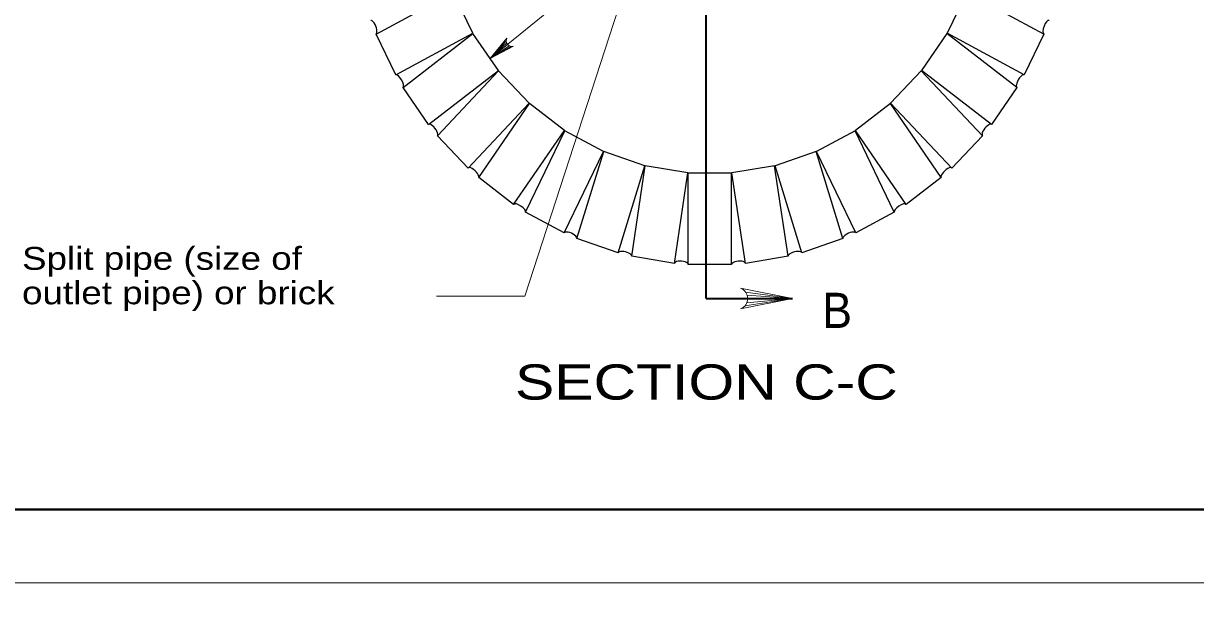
# Model space of a CAD drawing. Extents: x 1083.1 to 1117.1, y 697.4 to 741.4.
# Drawn here: x 1090.06 to 1098.04, y 719.1 to 723.17 of the extents above; entities that cross this region are included whole.
import ezdxf

# ---------------------------------------------------------------- set-up
doc = ezdxf.new("R2010")
doc.units = 0
doc.header["$LTSCALE"] = 0.062
doc.linetypes.add('LONG_DASHED', pattern=[7.5, 6, -1.5])
doc.layers.add('1', color=7, linetype='Continuous', lineweight=13)

msp = doc.modelspace()

# ---------------------------------------------------------------- linework, layer by layer
at = {"layer": '1', "lineweight": 35}
for p, q in [((1094.71067, 723.14725), (1094.71067, 723.88192)), ((1094.71067, 721.52408), (1094.71067, 723.14725)), ((1094.71067, 721.29192), (1094.71067, 721.52408)), ((1094.71067, 721.29192), (1095.29792, 721.29192))]:
    msp.add_line(p, q, dxfattribs=at)
at = {"layer": '1', "lineweight": 25}
for p, q in [((1092.46108, 723.09508), (1092.98608, 723.37833)), ((1093.11983, 723.10042), (1092.98608, 723.37833)), ((1096.48442, 723.37833), (1096.35067, 723.10042)), ((1097.00942, 723.09508), (1096.48442, 723.37833)), ((1092.59483, 722.81717), (1092.46108, 723.09508)), ((1092.59483, 722.81717), (1093.11983, 723.10042)), ((1092.64442, 722.73142), (1093.12117, 723.09808)), ((1093.29433, 722.84575), (1093.12117, 723.09808)), ((1096.34933, 723.09808), (1096.17617, 722.84575)), ((1096.826, 722.73142), (1096.34933, 723.09808)), ((1096.87567, 722.81717), (1096.35067, 723.10042)), ((1097.00942, 723.09508), (1096.87567, 722.81717)), ((1092.81767, 722.47908), (1093.29433, 722.84575)), ((1092.87933, 722.40258), (1093.296, 722.84367)), ((1093.50433, 722.62308), (1093.296, 722.84367)), ((1096.1745, 722.84367), (1095.96617, 722.62308)), ((1096.59117, 722.40258), (1096.1745, 722.84367)), ((1096.65283, 722.47908), (1096.17617, 722.84575)), ((1092.81767, 722.47908), (1092.64442, 722.73142)), ((1096.826, 722.73142), (1096.65283, 722.47908)), ((1093.08767, 722.182), (1093.50433, 722.62308)), ((1093.15992, 722.11667), (1093.50625, 722.62133)), ((1093.74467, 722.438), (1093.50625, 722.62133)), ((1095.96417, 722.62133), (1095.72583, 722.438)), ((1096.31058, 722.11667), (1095.96417, 722.62133)), ((1096.38283, 722.182), (1095.96617, 722.62308)), ((1093.39825, 721.93333), (1093.74467, 722.438)), ((1093.47933, 721.88075), (1093.74683, 722.43658)), ((1094.00933, 722.295), (1093.74683, 722.43658)), ((1095.72367, 722.43658), (1095.46117, 722.295)), ((1095.99117, 721.88075), (1095.72367, 722.43658)), ((1096.07217, 721.93333), (1095.72583, 722.438)), ((1093.08767, 722.182), (1092.87933, 722.40258)), ((1096.59117, 722.40258), (1096.38283, 722.182)), ((1093.74183, 721.73917), (1094.00933, 722.295)), ((1093.82958, 721.70067), (1094.01167, 722.29392)), ((1094.29192, 722.19758), (1094.01167, 722.29392)), ((1095.45883, 722.29392), (1095.17858, 722.19758)), ((1095.64092, 721.70067), (1095.45883, 722.29392)), ((1095.72867, 721.73917), (1095.46117, 722.295)), ((1094.10983, 721.60425), (1094.29192, 722.19758)), ((1094.20217, 721.58075), (1094.29442, 722.19692)), ((1094.58542, 722.14817), (1094.29442, 722.19692)), ((1095.17608, 722.19692), (1094.88508, 722.14817)), ((1095.26825, 721.58075), (1095.17608, 722.19692)), ((1095.36067, 721.60425), (1095.17858, 722.19758)), ((1093.39825, 721.93333), (1093.15992, 722.11667)), ((1094.49317, 721.532), (1094.58542, 722.14817)), ((1094.88258, 722.14792), (1094.58792, 722.14792)), ((1094.58792, 721.52408), (1094.58792, 722.14792)), ((1094.88258, 721.52408), (1094.88258, 722.14792)), ((1094.97725, 721.532), (1094.88508, 722.14817)), ((1096.31058, 722.11667), (1096.07217, 721.93333)), ((1093.74183, 721.73917), (1093.47933, 721.88075)), ((1095.99117, 721.88075), (1095.72867, 721.73917)), ((1094.10983, 721.60425), (1093.82958, 721.70067)), ((1095.64092, 721.70067), (1095.36067, 721.60425)), ((1094.49317, 721.532), (1094.20217, 721.58075)), ((1095.26825, 721.58075), (1094.97725, 721.532)), ((1094.88258, 721.52408), (1094.58792, 721.52408))]:
    msp.add_line(p, q, dxfattribs=at)
at = {"layer": '1'}
for p, q in [((1093.71942, 723.32042), (1093.23758, 722.92842)), ((1093.34775, 723.04692), (1093.23758, 722.92842)), ((1093.35058, 723.03492), (1093.23758, 722.92842)), ((1093.35642, 723.02508), (1093.23758, 722.92842)), ((1093.36767, 723.01567), (1093.23758, 722.92842)), ((1093.379, 723.0115), (1093.23758, 722.92842)), ((1094.9775, 721.33675), (1095.29792, 721.29192)), ((1094.98833, 721.3145), (1095.29792, 721.29192)), ((1094.97367, 721.24233), (1095.29792, 721.29192)), ((1094.98592, 721.26308), (1095.29792, 721.29192)), ((1094.99158, 721.29192), (1095.29792, 721.29192))]:
    msp.add_line(p, q, dxfattribs=at)
at = {"layer": '1', "linetype": 'LONG_DASHED'}
for points in [[(1083.12642, 719.35408), (1117.12642, 719.35408), (1117.12642, 741.35408), (1083.12642, 741.35408)], [(1083.12642, 697.35408), (1117.12642, 697.35408), (1117.12642, 719.35408), (1083.12642, 719.35408)]]:
    msp.add_lwpolyline(points, close=True, dxfattribs=at)
at = {"layer": '1', "lineweight": 25}
msp.add_lwpolyline([(1116.62642, 719.85408), (1085.12642, 719.85408), (1085.12642, 740.85408)], dxfattribs=at)
at = {"layer": '1', "lineweight": 40}
msp.add_lwpolyline([(1085.12642, 740.85408), (1116.62642, 740.85408), (1116.62642, 719.85408), (1085.12642, 719.85408)], close=True, dxfattribs=at)
at = {"layer": '1'}
for points in [[(1094.17225, 723.45483), (1093.47458, 721.3085), (1092.87242, 721.3085)], [(1093.39725, 723.01267), (1093.23758, 722.92842), (1093.35258, 723.06758)], [(1094.94392, 721.22108), (1095.29792, 721.29192), (1094.94392, 721.36267)]]:
    msp.add_lwpolyline(points, dxfattribs=at)
for centre, radius, start, end in [((1093.38596, 723.04916), 0.0382, 151.21802, 287.04414), ((1094.91536, 721.29196), 0.0764, 292.08605, 67.91218)]:
    msp.add_arc(centre, radius, start, end, dxfattribs=at)
at = {"layer": '1', "lineweight": 25}
for centre, major_axis, ratio, start_param, end_param in [((1092.44287, 723.14158), (-0.01791, 0.04658), 0.355583, 3.1580272, 6.2996199), ((1097.02761, 723.14157), (-0.01791, -0.04658), 0.355581, 3.1251606, 6.2667532), ((1092.61963, 722.7743), (-0.0245, 0.04308), 0.360529, 3.1626767, 6.3042693), ((1096.85084, 722.77429), (-0.0245, -0.04308), 0.360527, 3.1205104, 6.2621031), ((1092.84848, 722.44081), (-0.03053, 0.03852), 0.36655, 3.1654763, 6.307069), ((1096.62199, 722.44081), (-0.03052, -0.03853), 0.366547, 3.1177098, 6.2593025), ((1093.1238, 722.14933), (-0.03584, 0.033), 0.373137, 3.166043, 6.3076357), ((1096.34667, 722.14933), (-0.03583, -0.033), 0.373134, 3.117142, 6.2587347), ((1093.43879, 721.90704), (-0.04029, 0.02663), 0.379662, 3.1641623, 6.3057549), ((1096.03168, 721.90704), (-0.04029, -0.02663), 0.37966, 3.1190216, 6.2606142), ((1093.7857, 721.7199), (-0.04376, 0.01956), 0.385427, 3.1598674, 6.3014601), ((1095.68476, 721.7199), (-0.04376, -0.01956), 0.385425, 3.1233154, 6.2649081), ((1094.156, 721.59252), (-0.04614, 0.01196), 0.389747, 3.1535017, 6.2950944), ((1095.31447, 721.59252), (-0.04614, -0.01196), 0.389745, 3.1296802, 6.2712729), ((1094.54056, 721.52803), (-0.04736, 0.00402), 0.392063, 3.1457278, 6.2873205), ((1094.92991, 721.52803), (-0.04736, -0.00403), 0.392063, 3.1374537, 6.2790464)]:
    msp.add_ellipse(centre, major_axis=major_axis, ratio=ratio, start_param=start_param, end_param=end_param, dxfattribs=at)

# ---------------------------------------------------------------- texts
at = {"layer": '1'}
for s, height, width, p in [('Split pipe (size of', 0.156, 1.2, (1090.04942, 721.48808)), ('outlet pipe) or brick', 0.156, 1.2, (1090.04942, 721.25342)), ('B', 0.24, 0.95, (1095.49975, 721.09175)), ('SECTION C-C', 0.24, 1.25, (1093.40733, 720.6035))]:
    msp.add_text(s, height=height, dxfattribs=dict(at, width=width)).set_placement(p)

doc.saveas('drawing.dxf')
